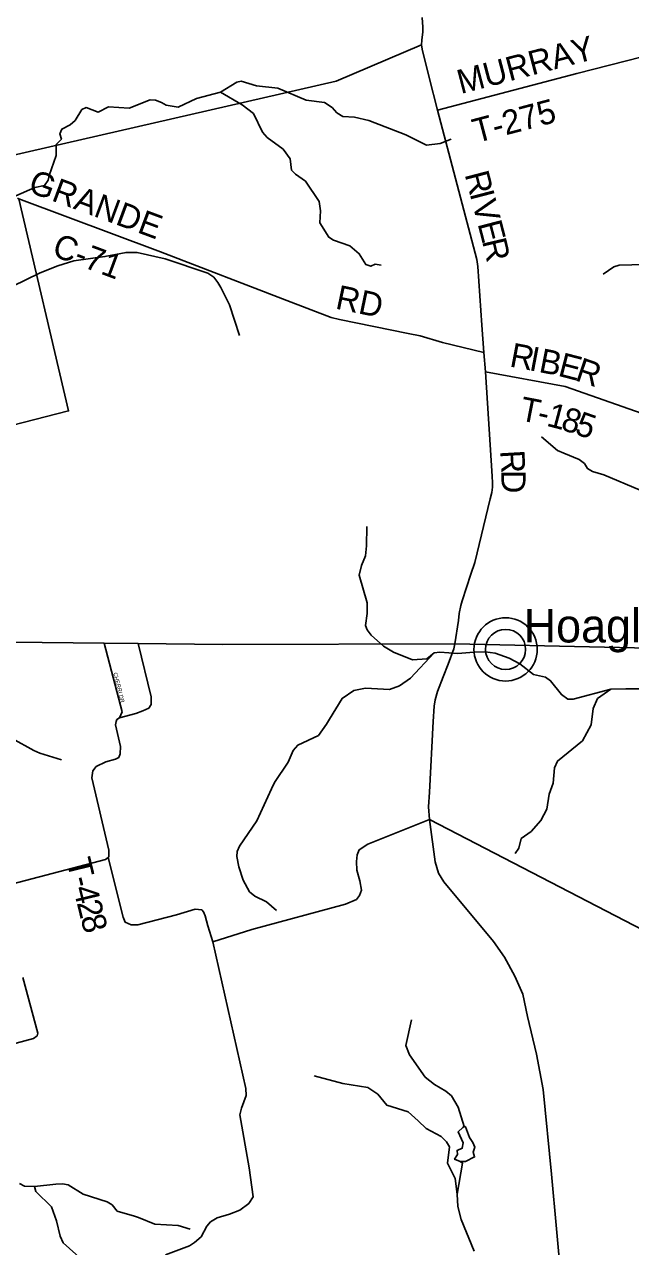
# Model space of a CAD drawing. Extents: x 1525783 to 1900577, y 218250 to 627376.
# Drawn here: x 1628572 to 1636103, y 433381 to 448562 of the extents above; entities that cross this region are included whole.
import ezdxf

# ---------------------------------------------------------------- set-up
doc = ezdxf.new("R2010")
doc.units = 0
for name, color, linetype in [('GM_X_County_Road', 7, 'Continuous'), ('GM_X_County_Road_Text', 7, 'Continuous'), ('GM_X_County_Subdivision', 7, 'Continuous'), ('GM_X_County_Subdivision_Text', 7, 'Continuous'), ('GM_X_Minor_Lake', 7, 'Continuous'), ('GM_X_Minor_River', 7, 'Continuous'), ('GM_X_Township', 7, 'Continuous'), ('GM_X_Township_Road', 7, 'Continuous'), ('GM_X_Township_Road_Text', 7, 'Continuous'), ('GM_X_Unincorporated', 7, 'Continuous'), ('GM_X_Unincorporated_Location', 7, 'Continuous'), ('GM_X_Unincorporated_Text', 7, 'Continuous'), ('GM_X_US_Route', 7, 'Continuous')]:
    doc.layers.add(name, color=color, linetype=linetype)

msp = doc.modelspace()

# ---------------------------------------------------------------- linework, layer by layer
at = {"layer": 'GM_X_County_Road'}
for points in [[(1633920, 440868), (1633965, 441157), (1633973, 441245), (1633994, 441345), (1634010, 441401), (1634120, 441735), (1634166, 441879), (1634357, 442669), (1634377, 442746), (1634389, 442816), (1634388, 442868), (1634383, 442951), (1634299, 444246), (1634279, 444485), (1634254, 444827), (1634205, 445557), (1634194, 445643), (1633703, 447497), (1633599, 447901), (1633514, 448254), (1633507, 448310), (1633510, 448365), (1633523, 448469), (1633522, 448530), (1633515, 448647)], [(1628486, 446402), (1628504, 446395), (1630263, 445738), (1631834, 445134), (1632382, 444921), (1632485, 444898), (1633339, 444723), (1633490, 444693), (1633765, 444611), (1634279, 444485)], [(1628333, 437863), (1629502, 438167), (1629579, 438191), (1629612, 438215), (1629622, 438222), (1629620, 438306), (1629411, 439203), (1629421, 439290), (1629463, 439343), (1629583, 439404), (1629702, 439435), (1629743, 439458), (1629762, 439501), (1629766, 439594), (1629703, 439862), (1629710, 439902), (1629721, 439928), (1629754, 439947), (1629957, 440001), (1630045, 440035), (1630116, 440071), (1630147, 440116), (1630147, 440208), (1629984, 440871)], [(1635246, 432924), (1635122, 434281), (1635018, 435332), (1634933, 435772), (1634821, 436240), (1634764, 436515), (1634666, 436740), (1634538, 436976), (1634401, 437169), (1633783, 437912), (1633718, 438018), (1633675, 438162), (1633605, 438688), (1633592, 438843), (1633604, 439025), (1633650, 439905), (1633662, 440094), (1633677, 440171), (1633703, 440275), (1633775, 440459), (1633837, 440617), (1633907, 440804), (1633920, 440868)], [(1630911, 437167), (1631399, 437321), (1632561, 437634), (1632697, 437694), (1632736, 437741), (1632760, 437807), (1632741, 437925), (1632700, 438055), (1632699, 438163), (1632707, 438247), (1632731, 438311), (1632837, 438378), (1633605, 438688)], [(1630324, 433277), (1630622, 433389), (1630687, 433431), (1630767, 433503), (1630839, 433634), (1630884, 433689), (1630968, 433740), (1631119, 433782), (1631247, 433833), (1631362, 433918), (1631414, 434000), (1631365, 434359), (1631248, 435016), (1631269, 435101), (1631327, 435256), (1631323, 435343), (1630911, 437167)], [(1627478, 435644), (1628686, 435967), (1628729, 435999), (1628737, 436033), (1628551, 436722)]]:
    msp.add_lwpolyline(points, dxfattribs=at)
at = {"layer": 'GM_X_County_Subdivision'}
msp.add_lwpolyline([(1629754, 439947), (1629786, 440022), (1629564, 440875)], dxfattribs=at)
at = {"layer": 'GM_X_Minor_Lake'}
for points in [[(1634017, 434862), (1633960, 434808), (1634022, 434669), (1634011, 434603), (1633947, 434576), (1633952, 434526), (1633916, 434465), (1633987, 434436), (1634051, 434437), (1634164, 434495), (1634147, 434554), (1634169, 434617), (1634144, 434674), (1634101, 434736), (1634053, 434869)], [(1634053, 434869), (1634045, 434876), (1634037, 434874), (1634017, 434862)]]:
    msp.add_lwpolyline(points, dxfattribs=at)
at = {"layer": 'GM_X_Minor_River'}
for points in [[(1628466, 446433), (1628701, 446538), (1628820, 446561), (1628868, 446628), (1628881, 446686), (1628966, 446933), (1628966, 447070), (1629031, 447137), (1629012, 447201), (1629038, 447263), (1629141, 447314), (1629202, 447369), (1629287, 447504), (1629339, 447529), (1629487, 447473), (1629617, 447540), (1629873, 447522), (1630136, 447625), (1630202, 447622), (1630277, 447593), (1630331, 447559), (1630482, 447535), (1630711, 447640), (1631010, 447722), (1631209, 447844), (1631265, 447857), (1631456, 447800), (1631720, 447771), (1632073, 447622), (1632302, 447591), (1632396, 447530), (1632455, 447465), (1632528, 447420), (1632672, 447408), (1632849, 447368), (1633312, 447189), (1633568, 447064), (1633738, 447084), (1633872, 447136)], [(1631010, 447722), (1631277, 447562), (1631420, 447454), (1631529, 447223), (1631586, 447158), (1631786, 447013), (1631872, 446892), (1631892, 446753), (1631939, 446701), (1632066, 446615), (1632235, 446362), (1632249, 446246), (1632241, 446098), (1632355, 445918), (1632412, 445883), (1632615, 445813), (1632732, 445713), (1632812, 445578), (1632875, 445559), (1632928, 445586), (1633003, 445573)], [(1638767, 446391), (1638690, 446338), (1638548, 446316), (1637958, 446139), (1637820, 446075), (1637703, 446035), (1637506, 446055), (1637307, 446002), (1637069, 445821), (1637011, 445811), (1636892, 445827), (1636758, 445849), (1636626, 445849), (1636514, 445792), (1636386, 445663), (1636277, 445581), (1635962, 445573), (1635895, 445552), (1635762, 445459)], [(1628418, 445307), (1628768, 445478), (1628987, 445563), (1629187, 445627), (1629571, 445678), (1629836, 445731), (1629971, 445727), (1630320, 445652), (1630851, 445471), (1630924, 445422), (1630975, 445357), (1631014, 445293), (1631121, 445077), (1631244, 444699)], [(1637927, 440461), (1637990, 440642), (1638111, 441373), (1638098, 441454), (1638002, 441585), (1637692, 441755), (1637455, 441933), (1637226, 442182), (1637189, 442237), (1637063, 442348), (1636825, 442512), (1636539, 442660), (1636221, 442776), (1635770, 442966), (1635629, 443008), (1635566, 443045), (1635530, 443107), (1635465, 443156), (1635272, 443237), (1635195, 443270), (1634995, 443439)], [(1633663, 440757), (1633572, 440680), (1633394, 440670), (1633159, 440763), (1633032, 440841), (1632880, 440975), (1632829, 441040), (1632810, 441094), (1632832, 441244), (1632832, 441378), (1632730, 441720), (1632758, 441842), (1632811, 441963), (1632821, 442085), (1632824, 442324)], [(1636218, 440311), (1636042, 440309), (1635856, 440304), (1635391, 440182), (1635325, 440181), (1635244, 440238), (1635110, 440410), (1635047, 440452), (1634898, 440486), (1634727, 440621), (1634595, 440691), (1634420, 440753), (1634298, 440769), (1634160, 440764), (1634106, 440759), (1633956, 440747), (1633733, 440766), (1633663, 440757), (1633369, 440440), (1633232, 440348), (1633109, 440300), (1632808, 440316), (1632664, 440287), (1632519, 440191), (1632362, 439933), (1632325, 439871), (1632225, 439730), (1631968, 439610), (1631909, 439544), (1631847, 439399), (1631678, 439147), (1631643, 439067), (1631459, 438669), (1631245, 438356), (1631216, 438290), (1631209, 438226)], [(1635856, 440304), (1635693, 440188), (1635639, 440064), (1635615, 439862), (1635506, 439664), (1635193, 439411), (1635158, 439328), (1635142, 439138), (1635090, 439002), (1635064, 438814), (1634986, 438673), (1634867, 438539), (1634744, 438448), (1634714, 438330), (1634671, 438263)], [(1628418, 439692), (1628687, 439542), (1628763, 439509), (1629033, 439426)], [(1631209, 438226), (1631234, 438098), (1631291, 437931), (1631369, 437789), (1631433, 437735), (1631578, 437665), (1631702, 437555)], [(1633383, 436199), (1633311, 435880), (1633357, 435763), (1633551, 435486), (1633668, 435393), (1633809, 435311), (1633876, 435252), (1633960, 435113), (1634037, 434874)], [(1633950, 434034), (1633925, 434228), (1633827, 434418), (1633852, 434620), (1633817, 434682), (1633748, 434749), (1633565, 434848), (1633464, 434945), (1633338, 435053), (1633073, 435136), (1632961, 435276), (1632840, 435356), (1632529, 435406), (1632173, 435502)], [(1633987, 434436), (1634015, 434419), (1633950, 434034)], [(1628509, 434163), (1628574, 434132), (1628698, 434128), (1628964, 434157), (1629044, 434162), (1629114, 434147), (1629302, 434032), (1629600, 433938), (1629662, 433898), (1629725, 433821), (1629938, 433760), (1629989, 433741), (1630192, 433660), (1630481, 433641), (1630631, 433599)], [(1628698, 434128), (1628715, 434066), (1628908, 433875), (1628972, 433700), (1629014, 433510), (1629053, 433427), (1629211, 433287), (1629451, 433069), (1629642, 432837), (1629817, 432428), (1629855, 432293)], [(1634161, 433326), (1633998, 433719), (1633958, 433879), (1633950, 434034)]]:
    msp.add_lwpolyline(points, dxfattribs=at)
at = {"layer": 'GM_X_Township'}
for points in [[(1633515, 448647), (1633522, 448530), (1633523, 448469), (1633510, 448365), (1633507, 448310), (1632446, 447856), (1628381, 446924)], [(1642041, 434318), (1633605, 438688), (1633592, 438843), (1633604, 439025), (1633650, 439905), (1633662, 440094), (1633677, 440171), (1633703, 440275), (1633775, 440459), (1633837, 440617), (1633907, 440804), (1633920, 440868), (1633965, 441157), (1633973, 441245), (1633994, 441345), (1634010, 441401), (1634120, 441735), (1634166, 441879), (1634357, 442669), (1634377, 442746), (1634389, 442816), (1634388, 442868), (1634383, 442951), (1634299, 444246), (1634279, 444485), (1634254, 444827), (1634205, 445557), (1634194, 445643), (1633703, 447497), (1633599, 447901), (1633514, 448254), (1633507, 448310), (1633510, 448365), (1633523, 448469), (1633522, 448530), (1633515, 448647)], [(1628381, 446924), (1632446, 447856), (1633507, 448310), (1633514, 448254), (1633599, 447901), (1633703, 447497), (1634194, 445643), (1634205, 445557), (1634254, 444827), (1634279, 444485), (1634299, 444246), (1634383, 442951), (1634388, 442868), (1634389, 442816), (1634377, 442746), (1634357, 442669), (1634166, 441879), (1634120, 441735), (1634010, 441401), (1633994, 441345), (1633973, 441245), (1633965, 441157), (1633920, 440868), (1633907, 440804), (1633837, 440617), (1633775, 440459), (1633703, 440275), (1633677, 440171), (1633662, 440094), (1633650, 439905), (1633604, 439025), (1633592, 438843), (1633605, 438688), (1642041, 434318)], [(1626156, 443002), (1629120, 443761), (1628504, 446395)], [(1628504, 446395), (1629120, 443761), (1626156, 443002)]]:
    msp.add_lwpolyline(points, dxfattribs=at)
at = {"layer": 'GM_X_Township_Road'}
for points in [[(1633703, 447497), (1635437, 447951), (1636245, 448159), (1637266, 448417), (1639044, 448906)], [(1634299, 444246), (1635290, 444066), (1636481, 443645), (1636563, 443625), (1636691, 443627), (1636860, 443647), (1637003, 443669), (1637237, 443646), (1638832, 443240), (1639415, 443089), (1639540, 443015), (1639687, 442921), (1639830, 442847), (1639927, 442816), (1641236, 442434), (1641684, 442299), (1641855, 442260), (1643086, 441808), (1645050, 441269), (1645109, 441250)], [(1630911, 437167), (1630852, 437365), (1630819, 437488), (1630796, 437541), (1630775, 437562), (1630695, 437574), (1630460, 437501), (1629980, 437376), (1629900, 437376), (1629822, 437412), (1629798, 437473), (1629612, 438215)]]:
    msp.add_lwpolyline(points, dxfattribs=at)
at = {"layer": 'GM_X_Unincorporated'}
for radius in [393, 249]:
    msp.add_circle((1634550, 440799), radius, dxfattribs=at)
at = {"layer": 'GM_X_Unincorporated_Location'}
msp.add_line((1634550, 440799), (1634550, 440799), dxfattribs=at)
at = {"layer": 'GM_X_US_Route'}
msp.add_lwpolyline([(1622451, 440961), (1623894, 440943), (1626649, 440908), (1627244, 440901), (1629564, 440875), (1629984, 440871), (1631031, 440859), (1633920, 440868), (1641356, 440703), (1643192, 440667)], dxfattribs=at)

# ---------------------------------------------------------------- texts
at = {"layer": 'GM_X_County_Road_Text'}
for s, rotation, p in [('GRANDE', 339.6371, (1628603, 446487)), ('R', 284.6109, (1634040, 446701)), ('I', 284.6099, (1634102, 446462)), ('V', 284.6117, (1634133, 446343)), ('E', 284.584, (1634200, 446088)), ('C-71', 339.6043, (1628900, 445694)), ('R', 283.2695, (1634256, 445872)), ('RD', 348.2202, (1632424, 445034)), ('R', 273.1963, (1634483, 443268)), ('D', 270.7122, (1634497, 443025))]:
    msp.add_text(s, height=300, rotation=rotation, dxfattribs=at).set_placement(p)
at = {"layer": 'GM_X_County_Subdivision_Text'}
msp.add_text('CHERRI DR', height=50, rotation=284.0355, dxfattribs=at).set_placement((1629676, 440505))
at = {"layer": 'GM_X_Township_Road_Text'}
for s, rotation, p in [('MURRAY', 14.6803, (1633993, 447696)), ('T-275', 14.786, (1634186, 447087)), ('R', 349.2944, (1634589, 444315)), ('I', 349.2961, (1634831, 444269)), ('B', 348.8332, (1634952, 444246)), ('E', 345.444, (1635189, 444200)), ('R', 341.3849, (1635401, 444145)), ('T', 348.9128, (1634711, 443647)), ('-', 347.5372, (1634930, 443605)), ('1', 345.1812, (1635047, 443579)), ('8', 342.6027, (1635222, 443533)), ('5', 341.064, (1635396, 443478)), ('T', 283.6038, (1629094, 438171)), ('-', 283.6202, (1629147, 437953)), ('4', 283.6842, (1629176, 437833)), ('2', 283.9339, (1629220, 437652)), ('8', 284.8, (1629266, 437468))]:
    msp.add_text(s, height=300, rotation=rotation, dxfattribs=at).set_placement(p)
at = {"layer": 'GM_X_Unincorporated_Text'}
msp.add_text('Hoagland', height=417, rotation=0, dxfattribs=at).set_placement((1634775, 440885))

doc.saveas('drawing.dxf')
